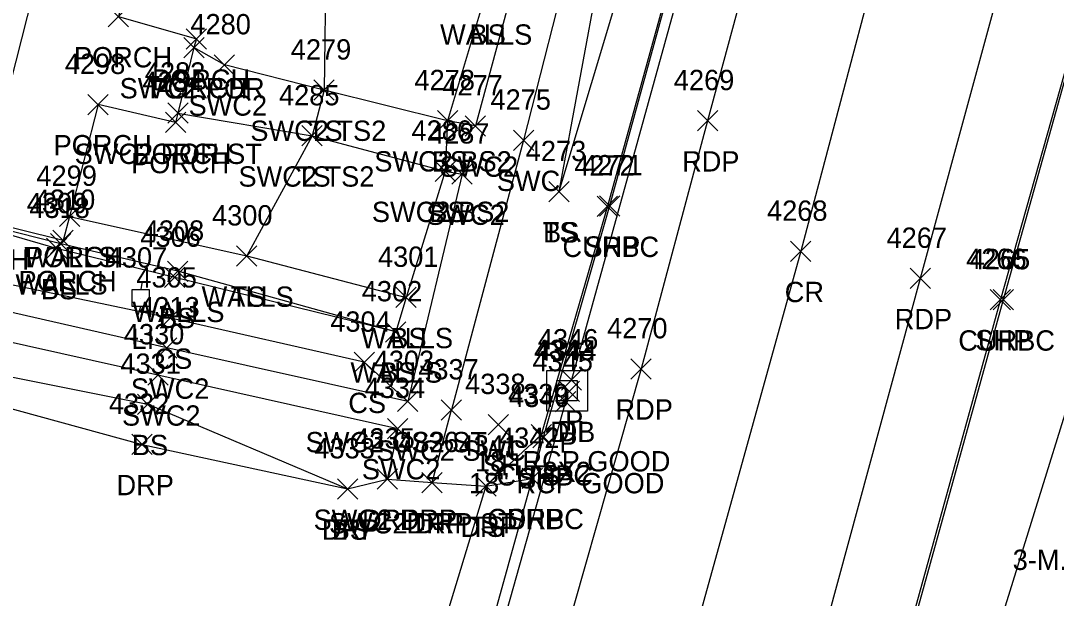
# Model space of a CAD drawing. Extents: x 1443912 to 1445411, y 621446 to 623693.
# Drawn here: x 1444888.1 to 1444990, y 623335.6 to 623392.4 of the extents above; entities that cross this region are included whole.
import ezdxf

# ---------------------------------------------------------------- set-up
doc = ezdxf.new("R2010")
doc.units = 0
for name, color, linetype in [('D_A', 7, 'Continuous'), ('D_C', 7, 'Continuous'), ('D_I', 7, 'Continuous'), ('D_TIC', 7, 'Continuous'), ('DCP', 7, 'Continuous'), ('DS', 7, 'Continuous'), ('L_A', 7, 'Continuous'), ('L_C', 7, 'Continuous'), ('L_I', 7, 'Continuous'), ('L_TIC', 7, 'Continuous'), ('LBC', 7, 'Continuous'), ('LBF', 7, 'Continuous'), ('LELB', 7, 'Continuous'), ('LWS', 7, 'Continuous'), ('P_A', 7, 'Continuous'), ('P_I', 7, 'Continuous'), ('P_TIC', 7, 'Continuous'), ('PET', 7, 'Continuous'), ('PRC', 7, 'Continuous'), ('PSP', 7, 'Continuous'), ('R_A', 7, 'Continuous'), ('R_I', 7, 'Continuous'), ('R_TIC', 7, 'Continuous'), ('RC', 7, 'Continuous'), ('RDP', 7, 'Continuous'), ('RSW', 7, 'Continuous'), ('U_A', 7, 'Continuous'), ('U_I', 7, 'Continuous'), ('ULP', 7, 'Continuous')]:
    doc.layers.add(name, color=color, linetype=linetype)

msp = doc.modelspace()

# ---------------------------------------------------------------- linework, layer by layer
at = {"layer": 'D_TIC'}
for points in [[(1444941.32, 623356.04), (1444943.32, 623358.04)], [(1444943.32, 623356.04), (1444941.32, 623358.04)], [(1444941.1, 623354.93), (1444943.1, 623356.93)], [(1444943.1, 623354.93), (1444941.1, 623356.93)], [(1444940.74, 623353.89), (1444942.74, 623355.89)], [(1444942.74, 623353.89), (1444940.74, 623355.89)]]:
    msp.add_lwpolyline(points, dxfattribs=at)
at = {"layer": 'DCP'}
for points in [[(1444991.54, 623534.89), (1444942.32, 623357.04)], [(1444941.74, 623354.89), (1444912.02, 623249.42)]]:
    msp.add_lwpolyline(points, dxfattribs=at)
at = {"layer": 'DS'}
for p, q in [((1444939.89, 623357.98), (1444943.89, 623357.98)), ((1444939.89, 623353.98), (1444939.89, 623357.98)), ((1444943.89, 623357.98), (1444943.89, 623353.98)), ((1444940.89, 623354.98), (1444940.89, 623356.98)), ((1444940.89, 623356.98), (1444942.89, 623356.98)), ((1444942.89, 623356.98), (1444942.89, 623354.98)), ((1444941.9, 623355.99), (1444941.9, 623355.99)), ((1444941.9, 623355.99), (1444941.9, 623355.99)), ((1444942.89, 623354.98), (1444940.89, 623354.98)), ((1444943.89, 623353.98), (1444939.89, 623353.98))]:
    msp.add_line(p, q, dxfattribs=at)
at = {"layer": 'L_TIC'}
for points in [[(1444896.74, 623391.78), (1444898.74, 623393.78)], [(1444898.74, 623391.78), (1444896.74, 623393.78)], [(1444904.42, 623389.58), (1444906.42, 623391.58)], [(1444906.42, 623389.58), (1444904.42, 623391.58)], [(1444904.16, 623388.73), (1444906.16, 623390.73)], [(1444906.16, 623388.73), (1444904.16, 623390.73)], [(1444916.97, 623384.55), (1444918.97, 623386.55)], [(1444918.97, 623384.55), (1444916.97, 623386.55)], [(1444894.73, 623383.13), (1444896.73, 623385.13)], [(1444896.73, 623383.13), (1444894.73, 623385.13)], [(1444902.6, 623382.28), (1444904.6, 623384.28)], [(1444904.6, 623382.28), (1444902.6, 623384.28)], [(1444902.36, 623381.37), (1444904.36, 623383.37)], [(1444904.36, 623381.37), (1444902.36, 623383.37)], [(1444929.13, 623381.54), (1444931.13, 623383.54)], [(1444931.13, 623381.54), (1444929.13, 623383.54)], [(1444915.8, 623380.05), (1444917.8, 623382.05)], [(1444917.8, 623380.05), (1444915.8, 623382.05)], [(1444928.89, 623376.57), (1444930.89, 623378.57)], [(1444930.89, 623376.57), (1444928.89, 623378.57)], [(1444940.08, 623374.56), (1444942.08, 623376.56)], [(1444942.08, 623374.56), (1444940.08, 623376.56)], [(1444940.08, 623374.56), (1444942.08, 623376.56)], [(1444942.08, 623374.56), (1444940.08, 623376.56)], [(1444891.94, 623372.13), (1444893.94, 623374.13)], [(1444893.94, 623372.13), (1444891.94, 623374.13)], [(1444891.94, 623372.13), (1444893.94, 623374.13)], [(1444893.94, 623372.13), (1444891.94, 623374.13)], [(1444890.66, 623368.97), (1444892.66, 623370.97)], [(1444892.66, 623368.97), (1444890.66, 623370.97)], [(1444891.07, 623369.44), (1444893.07, 623371.44)], [(1444893.07, 623369.44), (1444891.07, 623371.44)], [(1444891.29, 623369.77), (1444893.29, 623371.77)], [(1444893.29, 623369.77), (1444891.29, 623371.77)], [(1444909.37, 623368.23), (1444911.37, 623370.23)], [(1444911.37, 623368.23), (1444909.37, 623370.23)], [(1444909.37, 623368.23), (1444911.37, 623370.23)], [(1444911.37, 623368.23), (1444909.37, 623370.23)], [(1444902.28, 623366.13), (1444904.28, 623368.13)], [(1444904.28, 623366.13), (1444902.28, 623368.13)], [(1444902.57, 623366.73), (1444904.57, 623368.73)], [(1444904.57, 623366.73), (1444902.57, 623368.73)], [(1444925.05, 623364.16), (1444927.05, 623366.16)], [(1444927.05, 623364.16), (1444925.05, 623366.16)], [(1444925.05, 623364.16), (1444927.05, 623366.16)], [(1444927.05, 623364.16), (1444925.05, 623366.16)], [(1444901.85, 623362.13), (1444903.85, 623364.13)], [(1444903.85, 623362.13), (1444901.85, 623364.13)], [(1444924.02, 623360.77), (1444926.02, 623362.77)], [(1444926.02, 623360.77), (1444924.02, 623362.77)], [(1444924.02, 623360.77), (1444926.02, 623362.77)], [(1444926.02, 623360.77), (1444924.02, 623362.77)], [(1444920.92, 623357.78), (1444922.92, 623359.78)], [(1444922.92, 623357.78), (1444920.92, 623359.78)], [(1444899.62, 623353.64), (1444901.62, 623355.64)], [(1444901.62, 623353.64), (1444899.62, 623355.64)], [(1444925.2, 623353.92), (1444927.2, 623355.92)], [(1444927.2, 623353.92), (1444925.2, 623355.92)], [(1444934.11, 623351.65), (1444936.11, 623353.65)], [(1444936.11, 623351.65), (1444934.11, 623353.65)], [(1444938.35, 623350.65), (1444940.35, 623352.65)], [(1444940.35, 623350.65), (1444938.35, 623352.65)], [(1444932.9, 623345.6), (1444934.9, 623347.6)], [(1444934.9, 623345.6), (1444932.9, 623347.6)], [(1444919.28, 623345.32), (1444921.28, 623347.32)], [(1444921.28, 623345.32), (1444919.28, 623347.32)]]:
    msp.add_lwpolyline(points, dxfattribs=at)
at = {"layer": 'LBC'}
msp.add_lwpolyline([(1444874.93, 623413.13), (1444892.45, 623409.04), (1444892.85, 623408.75), (1444892.69, 623408.33), (1444883.66, 623372.89), (1444883.63, 623372.57), (1444883.28, 623372.4), (1444880.79, 623373.15), (1444876.87, 623374.34), (1444869.22, 623376.28)], dxfattribs=at)
at = {"layer": 'LBF'}
for points in [[(1444892.69, 623408.33), (1444901.14, 623406.01), (1444900.64, 623403.68), (1444897.74, 623392.78), (1444905.42, 623390.58), (1444905.16, 623389.73)], [(1444903.6, 623383.28), (1444903.36, 623382.37), (1444895.73, 623384.13), (1444892.94, 623373.13), (1444892.29, 623370.77), (1444883.66, 623372.89)]]:
    msp.add_lwpolyline(points, dxfattribs=at)
at = {"layer": 'LELB'}
for points in [[(1444999.5, 623624.29), (1445006.38, 623617.23), (1444999.2, 623587.78), (1444986.64, 623540.21), (1444984.08, 623533.25), (1444978.9, 623513.73), (1444970.81, 623477.4), (1444960.43, 623440.84), (1444953.7, 623417.64), (1444941.08, 623375.56)], [(1445097.52, 623539.22), (1445075.7, 623539.93), (1445051.11, 623545.39), (1445040.13, 623540.27), (1445036.37, 623522.01), (1445021.48, 623458.8), (1445005.96, 623403.97), (1444993.72, 623362.86), (1444977.79, 623311.56), (1444964.52, 623276.17), (1444977.62, 623272.11), (1444992.26, 623267.97), (1445018.74, 623260.17)], [(1444955.52, 623511.73), (1444964.94, 623508.39), (1444968.01, 623499.55), (1444966.57, 623478.12), (1444955.62, 623442.73), (1444949.06, 623418.88), (1444941.08, 623375.56)], [(1444918.15, 623398.22), (1444917.97, 623385.55), (1444916.8, 623381.05), (1444910.37, 623369.23)], [(1444933.85, 623395.01), (1444930.13, 623382.54), (1444929.89, 623377.57), (1444926.05, 623365.16)], [(1444926.2, 623354.92), (1444921.92, 623358.78), (1444902.85, 623363.13), (1444877.32, 623368.45), (1444880.79, 623373.15)], [(1444925.02, 623361.77), (1444903.28, 623367.13), (1444891.66, 623369.97), (1444883.28, 623372.4)], [(1444871.88, 623360.41), (1444900.62, 623354.64), (1444920.28, 623346.32)], [(1444939.35, 623351.65), (1444933.9, 623346.6), (1444924.82, 623316.71), (1444922.33, 623306.32), (1444917.3, 623287.16), (1444905.63, 623250.1), (1444894.04, 623244.55)]]:
    msp.add_lwpolyline(points, dxfattribs=at)
at = {"layer": 'LWS'}
msp.add_lwpolyline([(1444892.94, 623373.13), (1444910.37, 623369.23), (1444926.05, 623365.16), (1444925.02, 623361.77), (1444903.57, 623367.73), (1444892.07, 623370.44), (1444883.63, 623372.57)], dxfattribs=at)
at = {"layer": 'P_TIC'}
for points in [[(1444954.71, 623381.54), (1444956.71, 623383.54)], [(1444956.71, 623381.54), (1444954.71, 623383.54)], [(1444945.06, 623373.16), (1444947.06, 623375.16)], [(1444947.06, 623373.16), (1444945.06, 623375.16)], [(1444963.87, 623368.69), (1444965.87, 623370.69)], [(1444965.87, 623368.69), (1444963.87, 623370.69)], [(1444975.63, 623366.03), (1444977.63, 623368.03)], [(1444977.63, 623366.03), (1444975.63, 623368.03)], [(1444983.52, 623363.95), (1444985.52, 623365.95)], [(1444985.52, 623363.95), (1444983.52, 623365.95)], [(1444948.17, 623357.13), (1444950.17, 623359.13)], [(1444950.17, 623357.13), (1444948.17, 623359.13)], [(1444938.52, 623350.37), (1444940.52, 623352.37)], [(1444940.52, 623350.37), (1444938.52, 623352.37)], [(1444937.45, 623346.36), (1444939.45, 623348.36)], [(1444939.45, 623346.36), (1444937.45, 623348.36)]]:
    msp.add_lwpolyline(points, dxfattribs=at)
at = {"layer": 'PET'}
for points in [[(1445036.7, 623677.7), (1445026.38, 623639.78), (1445008.65, 623576.15), (1444996.95, 623532.89), (1444979.78, 623472.47), (1444964.83, 623416.22), (1444955.71, 623382.54), (1444949.17, 623358.13), (1444939.29, 623323.43), (1444926.27, 623275.91), (1444914.83, 623235.04), (1444901.53, 623186.46), (1444892.14, 623152.69), (1444883.14, 623119.13), (1444870.13, 623073.23), (1444861.49, 623043.31), (1444850.84, 623006.82), (1444834.61, 622954.83), (1444817.28, 622898.33)], [(1445060.04, 623670.52), (1445049.49, 623631.42), (1445031.61, 623567.44), (1445020.44, 623527.05), (1445003.5, 623465.59), (1444988.1, 623409.14), (1444976.63, 623367.03), (1444962.49, 623315.05), (1444949.49, 623267.35), (1444937.78, 623225.39), (1444926.09, 623182.22), (1444915.48, 623145.05), (1444906.98, 623113.48), (1444893.64, 623066.1), (1444886.06, 623037.31), (1444876.58, 623001.08), (1444863.33, 622947.05), (1444849.43, 622890.74)]]:
    msp.add_lwpolyline(points, dxfattribs=at)
at = {"layer": 'PRC'}
msp.add_lwpolyline([(1445048.12, 623674.07), (1445038.05, 623635.88), (1445020.14, 623572.7), (1445008.5, 623529.11), (1444991.68, 623469.75), (1444976.21, 623412.44), (1444964.87, 623369.69), (1444950.64, 623318.47), (1444938.05, 623272.58), (1444925.39, 623227.3), (1444913.85, 623184.57), (1444903.74, 623148.67), (1444894.97, 623116.18), (1444881.8, 623068.92), (1444873.97, 623040.25), (1444864.1, 623005.34), (1444846.73, 622950.74), (1444829.37, 622896.11)], dxfattribs=at)
at = {"layer": 'PSP'}
for points in [[(1445029.6, 623678.26), (1445021.68, 623649.55), (1445019.78, 623642.34), (1445019.32, 623640.93), (1445017.21, 623633.02), (1445017.08, 623631.73), (1445013.01, 623618.17), (1445011.68, 623612.99), (1445004.58, 623587.1), (1444990.43, 623535.38), (1444989.65, 623532.72), (1444983.26, 623509.22), (1444982.17, 623505.29), (1444973.63, 623474.39), (1444957.7, 623416.57), (1444946.06, 623374.16), (1444939.52, 623351.37), (1444938.45, 623347.36), (1444929.03, 623313.43)], [(1445068.04, 623668.61), (1445057.37, 623629.5), (1445040.05, 623566.3), (1445039.54, 623563.99), (1445035.08, 623546.36), (1445033.45, 623541.5), (1445028.92, 623524.87), (1445011.88, 623462.96), (1444996.28, 623406.54), (1444984.52, 623364.95), (1444970.17, 623313)]]:
    msp.add_lwpolyline(points, dxfattribs=at)
at = {"layer": 'R_TIC'}
for points in [[(1444904.16, 623388.73), (1444906.16, 623390.73)], [(1444906.16, 623388.73), (1444904.16, 623390.73)], [(1444907.17, 623387.03), (1444909.17, 623389.03)], [(1444909.17, 623387.03), (1444907.17, 623389.03)], [(1444916.97, 623384.55), (1444918.97, 623386.55)], [(1444918.97, 623384.55), (1444916.97, 623386.55)], [(1444902.6, 623382.28), (1444904.6, 623384.28)], [(1444904.6, 623382.28), (1444902.6, 623384.28)], [(1444929.13, 623381.54), (1444931.13, 623383.54)], [(1444931.13, 623381.54), (1444929.13, 623383.54)], [(1444915.8, 623380.05), (1444917.8, 623382.05)], [(1444917.8, 623380.05), (1444915.8, 623382.05)], [(1444931.87, 623381.02), (1444933.87, 623383.02)], [(1444933.87, 623381.02), (1444931.87, 623383.02)], [(1444936.61, 623379.62), (1444938.61, 623381.62)], [(1444938.61, 623379.62), (1444936.61, 623381.62)], [(1444928.89, 623376.57), (1444930.89, 623378.57)], [(1444930.89, 623376.57), (1444928.89, 623378.57)], [(1444930.56, 623376.29), (1444932.56, 623378.29)], [(1444932.56, 623376.29), (1444930.56, 623378.29)], [(1444944.85, 623373.13), (1444946.85, 623375.13)], [(1444946.85, 623373.13), (1444944.85, 623375.13)], [(1444983.8, 623363.92), (1444985.8, 623365.92)], [(1444985.8, 623363.92), (1444983.8, 623365.92)], [(1444901.49, 623359.19), (1444903.49, 623361.19)], [(1444903.49, 623359.19), (1444901.49, 623361.19)], [(1444900.62, 623356.54), (1444902.62, 623358.54)], [(1444902.62, 623356.54), (1444900.62, 623358.54)], [(1444925.2, 623353.92), (1444927.2, 623355.92)], [(1444927.2, 623353.92), (1444925.2, 623355.92)], [(1444929.5, 623353.09), (1444931.5, 623355.09)], [(1444931.5, 623353.09), (1444929.5, 623355.09)], [(1444929.5, 623353.09), (1444931.5, 623355.09)], [(1444931.5, 623353.09), (1444929.5, 623355.09)], [(1444924.22, 623351.26), (1444926.22, 623353.26)], [(1444926.22, 623351.26), (1444924.22, 623353.26)], [(1444938.35, 623350.65), (1444940.35, 623352.65)], [(1444940.35, 623350.65), (1444938.35, 623352.65)], [(1444899.06, 623349.7), (1444901.06, 623351.7)], [(1444901.06, 623349.7), (1444899.06, 623351.7)], [(1444923.21, 623346.29), (1444925.21, 623348.29)], [(1444925.21, 623346.29), (1444923.21, 623348.29)], [(1444923.21, 623346.29), (1444925.21, 623348.29)], [(1444925.21, 623346.29), (1444923.21, 623348.29)], [(1444927.6, 623345.94), (1444929.6, 623347.94)], [(1444929.6, 623345.94), (1444927.6, 623347.94)], [(1444927.6, 623345.94), (1444929.6, 623347.94)], [(1444929.6, 623345.94), (1444927.6, 623347.94)], [(1444932.9, 623345.6), (1444934.9, 623347.6)], [(1444934.9, 623345.6), (1444932.9, 623347.6)], [(1444937.45, 623346.36), (1444939.45, 623348.36)], [(1444939.45, 623346.36), (1444937.45, 623348.36)], [(1444937.45, 623346.36), (1444939.45, 623348.36)], [(1444939.45, 623346.36), (1444937.45, 623348.36)], [(1444919.28, 623345.32), (1444921.28, 623347.32)], [(1444921.28, 623345.32), (1444919.28, 623347.32)]]:
    msp.add_lwpolyline(points, dxfattribs=at)
at = {"layer": 'RC'}
for points in [[(1445035.08, 623546.36), (1445033.8, 623541.56), (1445029.25, 623524.79), (1445012.06, 623463.08), (1444996.39, 623406.47), (1444984.8, 623364.92), (1444970.42, 623313.05), (1444960.98, 623279.58), (1444959.91, 623275.87)], [(1444983.26, 623509.22), (1444981.83, 623505.36), (1444973.42, 623474.46), (1444957.56, 623416.57), (1444945.85, 623374.13), (1444939.35, 623351.65), (1444938.45, 623347.36)]]:
    msp.add_lwpolyline(points, dxfattribs=at)
at = {"layer": 'RDP'}
for points in [[(1444871.88, 623360.41), (1444871.92, 623358.39), (1444900.06, 623350.7), (1444920.28, 623346.32), (1444924.21, 623347.29)], [(1444928.6, 623346.94), (1444933.9, 623346.6), (1444938.45, 623347.36)]]:
    msp.add_lwpolyline(points, dxfattribs=at)
at = {"layer": 'RSW'}
for points in [[(1444949.32, 623444.86), (1444942.98, 623420.73), (1444937.55, 623399.4), (1444932.87, 623382.02), (1444930.13, 623382.54), (1444917.97, 623385.55), (1444908.17, 623388.03), (1444905.16, 623389.73), (1444903.6, 623383.28), (1444916.8, 623381.05), (1444929.89, 623377.57), (1444931.56, 623377.29), (1444926.2, 623354.92), (1444902.49, 623360.19), (1444873.29, 623366.86), (1444874.21, 623370.22), (1444875.65, 623369.85), (1444876.87, 623374.34)], [(1444953.94, 623443.54), (1444947.63, 623419.36), (1444942.47, 623399.79), (1444937.61, 623380.62), (1444930.5, 623354.09)], [(1444869.22, 623376.28), (1444867.95, 623371.69), (1444869.55, 623371.29), (1444867.23, 623361.66), (1444871.88, 623360.41), (1444872.66, 623363.99), (1444901.62, 623357.54), (1444925.22, 623352.26), (1444924.21, 623347.29), (1444928.6, 623346.94), (1444930.5, 623354.09)]]:
    msp.add_lwpolyline(points, dxfattribs=at)
at = {"layer": 'ULP'}
for p, q in [((1444900.09, 623366.76), (1444899.93, 623365.93)), ((1444899.09, 623364.26), (1444899.09, 623365.93)), ((1444899.09, 623365.93), (1444900.76, 623365.93)), ((1444900.76, 623365.93), (1444900.76, 623364.26)), ((1444899.93, 623365.09), (1444899.93, 623365.09)), ((1444900.76, 623364.26), (1444899.09, 623364.26)), ((1444899.68, 623363.43), (1444899.93, 623364.26))]:
    msp.add_line(p, q, dxfattribs=at)

# ---------------------------------------------------------------- texts
at = {"layer": 'D_A'}
for s, p in [('P', (1444941.7, 623352.04)), ('DIB', (1444940.2, 623350.93)), ('DI', (1444940.96, 623350.99)), ('P', (1444941.12, 623349.89))]:
    msp.add_text(s, height=2, dxfattribs=at).set_placement(p)
at = {"layer": 'D_C'}
for s, p in [('18" RCP GOOD', (1444932.82, 623348.04)), ('2X2', (1444939.47, 623346.99)), ('18" RCP GOOD', (1444932.23, 623345.89))]:
    msp.add_text(s, height=2, dxfattribs=at).set_placement(p)
at = {"layer": 'D_I'}
for s, p in [('4346', (1444939.01, 623360.04)), ('4343', (1444938.64, 623358.99)), ('4344', (1444938.84, 623358.93)), ('4345', (1444938.48, 623357.89))]:
    msp.add_text(s, height=2, dxfattribs=at).set_placement(p)
at = {"layer": 'L_A'}
for s, p in [('WALLS', (1444929.39, 623390.01)), ('BS', (1444932.29, 623390.01)), ('PORCH', (1444893.36, 623387.78)), ('PORCH', (1444901.04, 623385.58)), ('PORCH', (1444900.79, 623384.73)), ('TS', (1444916.38, 623380.55)), ('PORCH', (1444891.36, 623379.13)), ('PORCH', (1444899.22, 623378.28)), ('PORCH', (1444898.99, 623377.37)), ('BS', (1444928.57, 623377.54)), ('TS', (1444915.21, 623376.05)), ('BS', (1444928.33, 623372.57)), ('TS', (1444939.49, 623370.56)), ('BS', (1444939.52, 623370.56)), ('PORCH', (1444879.29, 623367.89)), ('WALLS', (1444888.48, 623368.13)), ('PORCH', (1444888.56, 623368.13)), ('PORCH', (1444887.91, 623365.77)), ('WALLS', (1444887.61, 623365.44)), ('BS', (1444890.1, 623364.97)), ('WALLS', (1444905.92, 623364.23)), ('TS', (1444908.78, 623364.23)), ('WALLS', (1444899.11, 623362.73)), ('BS', (1444901.72, 623362.13)), ('WALLS', (1444921.6, 623360.16)), ('BS', (1444924.49, 623360.16)), ('CS', (1444901.29, 623358.13)), ('WALLS', (1444920.57, 623356.77)), ('BS', (1444923.46, 623356.77)), ('CS', (1444920.36, 623353.78)), ('BS', (1444899.06, 623349.64)), ('CS', (1444924.64, 623349.92)), ('SH', (1444933.6, 623347.65)), ('TS', (1444937.75, 623346.65)), ('BS', (1444918.72, 623341.32)), ('TS', (1444932.31, 623341.6))]:
    msp.add_text(s, height=2, dxfattribs=at).set_placement(p)
at = {"layer": 'L_C'}
msp.add_text('3-M.CEDARS', height=2, dxfattribs=at).set_placement((1444985.73, 623338.35))
at = {"layer": 'L_I'}
for s, p in [('4279', (1444914.7, 623388.55)), ('4298', (1444892.47, 623387.13)), ('4283', (1444900.34, 623386.28)), ('4284', (1444900.1, 623385.37)), ('4278', (1444926.87, 623385.54)), ('4285', (1444913.54, 623384.05)), ('4286', (1444926.57, 623380.57)), ('4273', (1444937.82, 623378.56)), ('4273', (1444937.82, 623378.56)), ('4299', (1444889.67, 623376.13)), ('4299', (1444889.67, 623376.13)), ('4309', (1444888.72, 623373.44)), ('4318', (1444888.97, 623372.97)), ('4310', (1444889.51, 623373.77)), ('4300', (1444906.95, 623372.23)), ('4300', (1444906.95, 623372.23)), ('4306', (1444899.89, 623370.13)), ('4308', (1444900.23, 623370.73)), ('4301', (1444923.28, 623368.16)), ('4301', (1444923.28, 623368.16)), ('4305', (1444899.51, 623366.13)), ('4302', (1444921.68, 623364.77)), ('4302', (1444921.68, 623364.77)), ('4304', (1444918.58, 623361.78)), ('4331', (1444897.93, 623357.64)), ('4303', (1444922.86, 623357.92)), ('4338', (1444931.85, 623355.65)), ('4339', (1444936.08, 623354.65)), ('4341', (1444931.21, 623349.6)), ('4333', (1444917.02, 623349.32))]:
    msp.add_text(s, height=2, dxfattribs=at).set_placement(p)
at = {"layer": 'P_A'}
for s, p in [('RDP', (1444953.2, 623377.54)), ('SHP', (1444943.59, 623369.16)), ('CR', (1444963.3, 623364.69)), ('RDP', (1444974.12, 623362.03)), ('SHP', (1444982.05, 623359.95)), ('RDP', (1444946.65, 623353.13)), ('SHP', (1444937.06, 623346.37)), ('SHP', (1444935.99, 623342.36))]:
    msp.add_text(s, height=2, dxfattribs=at).set_placement(p)
at = {"layer": 'P_I'}
for s, p in [('4269', (1444952.39, 623385.54)), ('4271', (1444943.36, 623377.16)), ('4268', (1444961.56, 623372.69)), ('4267', (1444973.32, 623370.03)), ('4266', (1444981.15, 623367.95)), ('4270', (1444945.82, 623361.13)), ('4340', (1444936.18, 623354.37)), ('4342', (1444935.19, 623350.36))]:
    msp.add_text(s, height=2, dxfattribs=at).set_placement(p)
at = {"layer": 'R_A'}
for s, p in [('SWC2 POR', (1444897.86, 623384.73)), ('SWC2', (1444904.64, 623383.03)), ('SWC2 TS2', (1444910.72, 623380.55)), ('SWC2 POR ST', (1444893.43, 623378.28)), ('SWC2 BS2', (1444922.92, 623377.54)), ('SWC2', (1444929.34, 623377.02)), ('SWC2 TS2', (1444909.55, 623376.05)), ('SWC', (1444934.97, 623375.62)), ('SWC2 BS2', (1444922.68, 623372.57)), ('SWC2', (1444928.03, 623372.29)), ('CURBC', (1444941.43, 623369.13)), ('CURBC', (1444980.38, 623359.92)), ('SWC2', (1444898.96, 623355.19)), ('SWC2', (1444898.09, 623352.54)), ('SWC2 CS2 ST', (1444916.16, 623349.92)), ('SWC2 SWC', (1444923.11, 623349.09)), ('SWC2 SWC', (1444923.11, 623349.09)), ('SWC2', (1444921.69, 623347.26)), ('CURBC', (1444934.93, 623346.65)), ('DRP', (1444897.55, 623345.7)), ('CURBC', (1444934.03, 623342.36)), ('DRP', (1444935.94, 623342.36)), ('SWC2 DRP', (1444916.94, 623342.29)), ('SWC2 DRP ST', (1444918.46, 623341.94)), ('DRP', (1444921.7, 623342.29)), ('DRP', (1444926.08, 623341.94)), ('DRP', (1444931.39, 623341.6)), ('DRP', (1444917.76, 623341.32))]:
    msp.add_text(s, height=2, dxfattribs=at).set_placement(p)
at = {"layer": 'R_I'}
for s, p in [('4280', (1444904.82, 623391.03)), ('4279', (1444914.7, 623388.55)), ('4283', (1444900.34, 623386.28)), ('4278', (1444926.87, 623385.54)), ('4277', (1444929.61, 623385.02)), ('4285', (1444913.54, 623384.05)), ('4275', (1444934.35, 623383.62)), ('4286', (1444926.57, 623380.57)), ('4287', (1444928.3, 623380.29)), ('4272', (1444942.59, 623377.13)), ('4265', (1444981.5, 623367.92)), ('4313', (1444899.79, 623363.19)), ('4330', (1444898.27, 623360.54)), ('4303', (1444922.86, 623357.92)), ('4337', (1444927.24, 623357.09)), ('4337', (1444927.24, 623357.09)), ('4334', (1444921.96, 623355.26)), ('4339', (1444936.08, 623354.65)), ('4332', (1444896.8, 623353.7)), ('4335', (1444920.95, 623350.29)), ('4335', (1444920.95, 623350.29)), ('4336', (1444925.28, 623349.94)), ('4336', (1444925.28, 623349.94)), ('4341', (1444931.21, 623349.6)), ('4342', (1444935.19, 623350.36)), ('4342', (1444935.19, 623350.36)), ('4333', (1444917.02, 623349.32))]:
    msp.add_text(s, height=2, dxfattribs=at).set_placement(p)
at = {"layer": 'U_A'}
msp.add_text('LI', height=2, dxfattribs=at).set_placement((1444899.03, 623360.09))
at = {"layer": 'U_I'}
msp.add_text('4307', height=2, dxfattribs=at).set_placement((1444896.59, 623368.09))

doc.saveas('drawing.dxf')
